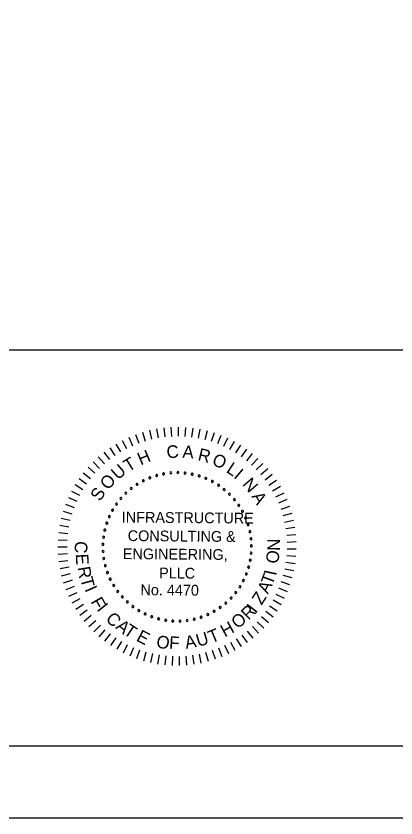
# Model space of a CAD drawing. Extents: x -121.2 to -24.9, y 6.4 to 65.7.
# Drawn here: x -53.92 to -46.89, y 6.35 to 21.19 of the extents above; entities that cross this region are included whole.
import ezdxf

# ---------------------------------------------------------------- set-up
doc = ezdxf.new("R2010")
doc.units = 0
for name, color, linetype in [('BR_BORDER LINES', 7, 'Continuous'), ('BR_TEXT', 7, 'Continuous'), ('Level 31', 7, 'Continuous')]:
    doc.layers.add(name, color=color, linetype=linetype)

msp = doc.modelspace()

# ---------------------------------------------------------------- linework, layer by layer
at = {"layer": 'BR_BORDER LINES'}
for p, q in [((-60.804, 15.017), (-46.496, 15.017)), ((-116.272, 7.683), (-26.496, 7.683))]:
    msp.add_line(p, q, dxfattribs=at)
at = {"layer": 'BR_TEXT'}
for p, q in [((-51.453, 13.526), (-51.413, 13.36)), ((-51.321, 13.553), (-51.292, 13.386)), ((-51.188, 13.572), (-51.169, 13.403)), ((-51.054, 13.583), (-51.045, 13.413)), ((-50.919, 13.586), (-50.921, 13.416)), ((-50.785, 13.58), (-50.796, 13.411)), ((-50.651, 13.567), (-50.673, 13.399)), ((-50.518, 13.545), (-50.55, 13.378)), ((-50.387, 13.515), (-50.429, 13.351)), ((-51.835, 13.396), (-51.766, 13.241)), ((-51.711, 13.447), (-51.651, 13.288)), ((-51.583, 13.49), (-51.533, 13.328)), ((-50.257, 13.478), (-50.31, 13.316)), ((-50.131, 13.432), (-50.193, 13.274)), ((-50.007, 13.379), (-50.079, 13.225)), ((-52.074, 13.272), (-51.987, 13.127)), ((-51.957, 13.338), (-51.878, 13.187)), ((-49.887, 13.318), (-49.968, 13.169)), ((-49.77, 13.251), (-49.86, 13.106)), ((-52.296, 13.12), (-52.192, 12.986)), ((-52.187, 13.2), (-52.091, 13.06)), ((-49.659, 13.176), (-49.757, 13.037)), ((-49.551, 13.094), (-49.658, 12.962)), ((-52.498, 12.942), (-52.378, 12.822)), ((-52.4, 13.034), (-52.287, 12.907)), ((-49.449, 13.006), (-49.564, 12.881)), ((-52.59, 12.844), (-52.463, 12.732)), ((-49.353, 12.913), (-49.475, 12.794)), ((-49.262, 12.813), (-49.391, 12.702)), ((-52.757, 12.633), (-52.617, 12.536)), ((-52.677, 12.741), (-52.543, 12.636)), ((-49.178, 12.708), (-49.313, 12.606)), ((-52.83, 12.52), (-52.684, 12.432)), ((-49.1, 12.598), (-49.242, 12.504)), ((-49.029, 12.484), (-49.176, 12.398)), ((-52.896, 12.402), (-52.745, 12.324)), ((-48.966, 12.365), (-49.117, 12.289)), ((-52.954, 12.281), (-52.799, 12.212)), ((-48.909, 12.243), (-49.065, 12.176)), ((-53.049, 12.029), (-52.887, 11.98)), ((-53.006, 12.157), (-52.847, 12.097)), ((-48.86, 12.117), (-49.02, 12.06)), ((-53.085, 11.9), (-52.92, 11.86)), ((-48.819, 11.989), (-48.982, 11.942)), ((-53.113, 11.768), (-52.946, 11.738)), ((-48.786, 11.859), (-48.951, 11.822)), ((-53.132, 11.635), (-52.964, 11.615)), ((-48.76, 11.727), (-48.928, 11.7)), ((-48.743, 11.593), (-48.912, 11.576)), ((-53.144, 11.501), (-52.974, 11.491)), ((-48.734, 11.459), (-48.904, 11.452)), ((-53.147, 11.366), (-52.978, 11.367)), ((-48.734, 11.324), (-48.903, 11.328)), ((-53.142, 11.231), (-52.973, 11.243)), ((-48.741, 11.19), (-48.91, 11.204)), ((-53.129, 11.097), (-52.961, 11.119)), ((-53.108, 10.965), (-52.941, 10.997)), ((-48.757, 11.056), (-48.925, 11.081)), ((-53.079, 10.833), (-52.914, 10.875)), ((-48.812, 10.793), (-48.976, 10.838)), ((-48.78, 10.923), (-48.947, 10.958)), ((-53.042, 10.704), (-52.88, 10.756)), ((-48.852, 10.664), (-49.013, 10.719)), ((-52.997, 10.577), (-52.838, 10.639)), ((-48.899, 10.538), (-49.056, 10.603)), ((-52.944, 10.453), (-52.79, 10.524)), ((-52.884, 10.333), (-52.734, 10.413)), ((-48.954, 10.415), (-49.107, 10.489)), ((-52.816, 10.216), (-52.672, 10.306)), ((-49.086, 10.181), (-49.229, 10.273)), ((-49.017, 10.296), (-49.165, 10.379)), ((-52.742, 10.104), (-52.603, 10.202)), ((-52.661, 9.996), (-52.529, 10.103)), ((-49.163, 10.07), (-49.3, 10.17)), ((-52.573, 9.894), (-52.448, 10.008)), ((-49.335, 9.863), (-49.459, 9.98)), ((-49.246, 9.964), (-49.376, 10.073)), ((-52.48, 9.797), (-52.362, 9.919)), ((-52.381, 9.706), (-52.27, 9.835)), ((-49.532, 9.679), (-49.64, 9.81)), ((-49.431, 9.768), (-49.547, 9.892)), ((-52.276, 9.622), (-52.173, 9.757)), ((-52.166, 9.543), (-52.072, 9.685)), ((-49.749, 9.521), (-49.841, 9.663)), ((-49.638, 9.597), (-49.738, 9.734)), ((-52.052, 9.472), (-51.967, 9.619)), ((-51.934, 9.408), (-51.858, 9.56)), ((-51.812, 9.351), (-51.745, 9.507)), ((-49.984, 9.389), (-50.058, 9.542)), ((-49.864, 9.451), (-49.947, 9.6)), ((-51.687, 9.302), (-51.629, 9.461)), ((-51.559, 9.26), (-51.511, 9.423)), ((-51.428, 9.226), (-51.391, 9.392)), ((-51.296, 9.2), (-51.269, 9.368)), ((-50.626, 9.194), (-50.65, 9.362)), ((-50.493, 9.217), (-50.528, 9.384)), ((-50.362, 9.249), (-50.407, 9.412)), ((-50.233, 9.288), (-50.288, 9.449)), ((-50.107, 9.335), (-50.171, 9.492)), ((-51.163, 9.183), (-51.146, 9.352)), ((-51.028, 9.173), (-51.022, 9.343)), ((-50.894, 9.172), (-50.898, 9.342)), ((-50.759, 9.179), (-50.773, 9.348))]:
    msp.add_line(p, q, dxfattribs=at)
for centre, start, end in [((-51.445, 12.647), 21.6807, 201.6807), ((-51.445, 12.647), 201.6807, 21.6807), ((-51.319, 12.689), 16.1422, 196.1422), ((-51.319, 12.689), 196.1422, 16.1422), ((-51.19, 12.72), 10.6038, 190.6038), ((-51.19, 12.72), 190.6038, 10.6038), ((-51.058, 12.738), 5.0653, 185.0653), ((-51.058, 12.738), 185.0653, 5.0653), ((-50.926, 12.743), 359.5268, 179.5268), ((-50.926, 12.743), 179.5268, 359.5268), ((-50.793, 12.735), 353.9884, 173.9884), ((-50.793, 12.735), 173.9884, 353.9884), ((-50.662, 12.714), 348.4499, 168.4499), ((-50.662, 12.714), 168.4499, 348.4499), ((-50.533, 12.681), 162.9114, 342.9114), ((-50.533, 12.681), 342.9114, 162.9114), ((-50.408, 12.636), 157.373, 337.373), ((-50.408, 12.636), 337.373, 157.373), ((-51.682, 12.526), 32.7576, 212.7576), ((-51.682, 12.526), 212.7576, 32.7576), ((-51.566, 12.592), 27.2191, 207.2191), ((-51.566, 12.592), 207.2191, 27.2191), ((-50.288, 12.579), 151.8345, 331.8345), ((-50.288, 12.579), 331.8345, 151.8345), ((-50.174, 12.51), 146.2961, 326.2961), ((-50.174, 12.51), 326.2961, 146.2961), ((-51.89, 12.362), 43.8345, 223.8345), ((-51.89, 12.362), 223.8345, 43.8345), ((-51.79, 12.449), 38.2961, 218.2961), ((-51.79, 12.449), 218.2961, 38.2961), ((-50.068, 12.431), 140.7576, 320.7576), ((-50.068, 12.431), 320.7576, 140.7576), ((-49.969, 12.342), 135.2191, 315.2191), ((-49.969, 12.342), 315.2191, 135.2191), ((-52.063, 12.16), 54.9114, 234.9114), ((-52.063, 12.16), 234.9114, 54.9114), ((-51.982, 12.265), 49.373, 229.373), ((-51.982, 12.265), 229.373, 49.373), ((-49.88, 12.244), 129.6807, 309.6807), ((-49.88, 12.244), 309.6807, 129.6807), ((-52.135, 12.048), 60.4499, 240.4499), ((-52.135, 12.048), 240.4499, 60.4499), ((-49.8, 12.137), 124.1422, 304.1422), ((-49.8, 12.137), 304.1422, 124.1422), ((-49.731, 12.024), 118.6038, 298.6038), ((-49.731, 12.024), 298.6038, 118.6038), ((-52.195, 11.93), 65.9884, 245.9884), ((-52.195, 11.93), 245.9884, 65.9884), ((-49.673, 11.904), 113.0653, 293.0653), ((-49.673, 11.904), 293.0653, 113.0653), ((-52.243, 11.806), 71.5268, 251.5268), ((-52.243, 11.806), 251.5268, 71.5268), ((-49.628, 11.779), 107.5268, 287.5268), ((-49.628, 11.779), 287.5268, 107.5268), ((-52.279, 11.678), 77.0653, 257.0653), ((-52.279, 11.678), 257.0653, 77.0653), ((-49.594, 11.651), 101.9884, 281.9884), ((-49.594, 11.651), 281.9884, 101.9884), ((-52.314, 11.415), 88.1422, 268.1422), ((-52.303, 11.547), 82.6038, 262.6038), ((-52.314, 11.415), 268.1422, 88.1422), ((-52.303, 11.547), 262.6038, 82.6038), ((-49.573, 11.519), 96.4499, 276.4499), ((-49.573, 11.519), 276.4499, 96.4499), ((-52.312, 11.282), 93.6807, 273.6807), ((-52.312, 11.282), 273.6807, 93.6807), ((-49.565, 11.387), 90.9114, 270.9114), ((-49.565, 11.387), 270.9114, 90.9114), ((-52.298, 11.15), 99.2191, 279.2191), ((-52.298, 11.15), 279.2191, 99.2191), ((-49.587, 11.122), 79.8345, 259.8345), ((-49.587, 11.122), 259.8345, 79.8345), ((-49.569, 11.254), 85.373, 265.373), ((-49.569, 11.254), 265.373, 85.373), ((-52.27, 11.02), 104.7576, 284.7576), ((-52.27, 11.02), 284.7576, 104.7576), ((-49.617, 10.993), 74.2961, 254.2961), ((-49.617, 10.993), 254.2961, 74.2961), ((-52.231, 10.893), 110.2961, 290.2961), ((-52.231, 10.893), 290.2961, 110.2961), ((-49.659, 10.867), 68.7576, 248.7576), ((-49.659, 10.867), 248.7576, 68.7576), ((-52.179, 10.771), 115.8345, 295.8345), ((-52.179, 10.771), 295.8345, 115.8345), ((-49.713, 10.746), 63.2191, 243.2191), ((-49.713, 10.746), 243.2191, 63.2191), ((-52.115, 10.654), 121.373, 301.373), ((-52.115, 10.654), 301.373, 121.373), ((-52.041, 10.544), 126.9114, 306.9114), ((-52.041, 10.544), 306.9114, 126.9114), ((-49.856, 10.522), 52.1422, 232.1422), ((-49.779, 10.63), 57.6807, 237.6807), ((-49.779, 10.63), 237.6807, 57.6807), ((-51.956, 10.441), 132.4499, 312.4499), ((-51.956, 10.441), 312.4499, 132.4499), ((-49.942, 10.421), 46.6038, 226.6038), ((-49.942, 10.421), 226.6038, 46.6038), ((-49.856, 10.522), 232.1422, 52.1422), ((-51.862, 10.348), 137.9884, 317.9884), ((-51.862, 10.348), 317.9884, 137.9884), ((-51.759, 10.263), 143.5268, 323.5268), ((-51.759, 10.263), 323.5268, 143.5268), ((-50.143, 10.247), 35.5268, 215.5268), ((-50.143, 10.247), 215.5268, 35.5268), ((-50.038, 10.329), 41.0653, 221.0653), ((-50.038, 10.329), 221.0653, 41.0653), ((-51.649, 10.189), 149.0653, 329.0653), ((-51.649, 10.189), 329.0653, 149.0653), ((-51.532, 10.126), 154.6038, 334.6038), ((-51.532, 10.126), 334.6038, 154.6038), ((-50.373, 10.115), 24.4499, 204.4499), ((-50.373, 10.115), 204.4499, 24.4499), ((-50.255, 10.175), 29.9884, 209.9884), ((-50.255, 10.175), 209.9884, 29.9884), ((-51.409, 10.075), 160.1422, 340.1422), ((-51.409, 10.075), 340.1422, 160.1422), ((-51.283, 10.036), 345.6807, 165.6807), ((-51.283, 10.036), 165.6807, 345.6807), ((-51.152, 10.009), 351.2191, 171.2191), ((-51.152, 10.009), 171.2191, 351.2191), ((-51.02, 9.995), 356.7576, 176.7576), ((-51.02, 9.995), 176.7576, 356.7576), ((-50.887, 9.993), 2.2961, 182.2961), ((-50.887, 9.993), 182.2961, 2.2961), ((-50.755, 10.005), 7.8345, 187.8345), ((-50.755, 10.005), 187.8345, 7.8345), ((-50.624, 10.029), 13.373, 193.373), ((-50.624, 10.029), 193.373, 13.373), ((-50.497, 10.066), 18.9114, 198.9114), ((-50.497, 10.066), 198.9114, 18.9114)]:
    msp.add_arc(centre, 0.0187, start, end, dxfattribs=at)
at = {"layer": 'Level 31'}
msp.add_lwpolyline([(-121.161, 6.35), (-25.161, 6.35), (-25.161, 65.017), (-121.161, 65.017)], close=True, dxfattribs=at)

# ---------------------------------------------------------------- texts
at = {"layer": 'BR_TEXT'}
for s, height, rotation, p in [('C', 0.233, 4.7281, (-51.127, 13.006)), ('A', 0.233, 355.6981, (-50.848, 13.019)), ('H', 0.233, 22.7882, (-51.615, 12.874)), ('R', 0.233, 346.6681, (-50.57, 12.974)), ('O', 0.233, 337.638, (-50.31, 12.894)), ('T', 0.233, 31.8182, (-51.841, 12.747)), ('L', 0.233, 327.108, (-50.046, 12.759)), ('U', 0.233, 40.8482, (-52.036, 12.597)), ('I', 0.233, 319.578, (-49.906, 12.659)), ('O', 0.233, 49.8782, (-52.215, 12.408)), ('N', 0.233, 310.548, (-49.744, 12.523)), ('S', 0.233, 58.9083, (-52.363, 12.199)), ('A', 0.233, 301.5179, (-49.57, 12.303)), ('INFRASTRUCTURE', 0.19939, 359.5268, (-51.966, 11.819)), ('CONSULTING &', 0.19939, 359.5268, (-51.856, 11.476)), ('C', 0.233, 267.025, (-52.829, 11.479)), ('N', 0.233, 89.2085, (-49.039, 11.293)), ('ENGINEERING,', 0.19939, 359.5268, (-51.946, 11.142)), ('O', 0.233, 83.2085, (-49.068, 11.05)), ('E', 0.233, 273.025, (-52.818, 11.235)), ('R', 0.233, 279.025, (-52.784, 10.989)), ('PLLC', 0.1994, 359.5268, (-51.275, 10.786)), ('T', 0.233, 69.3954, (-49.178, 10.645)), ('I', 0.233, 77.9093, (-49.11, 10.825)), ('T', 0.233, 285.025, (-52.737, 10.779)), ('A', 0.233, 63.3954, (-49.26, 10.484)), ('I', 0.233, 293.7713, (-52.658, 10.584)), ('No. 4470', 0.1994, 359.5268, (-51.62, 10.474)), ('Z', 0.233, 57.3954, (-49.377, 10.28)), ('F', 0.233, 299.7713, (-52.548, 10.355)), ('I', 0.233, 308.5268, (-52.436, 10.211)), ('R', 0.233, 44.5268, (-49.619, 10)), ('I', 0.233, 52.3339, (-49.487, 10.127)), ('C', 0.233, 314.5268, (-52.278, 10.024)), ('O', 0.233, 38.5268, (-49.823, 9.841)), ('A', 0.233, 320.5268, (-52.093, 9.868)), ('T', 0.233, 326.5268, (-51.948, 9.765)), ('H', 0.233, 28.5268, (-50.058, 9.691)), ('E', 0.233, 332.5268, (-51.712, 9.638)), ('T', 0.233, 22.5268, (-50.306, 9.58)), ('O', 0.233, 350.5268, (-51.338, 9.508)), ('F', 0.233, 356.5268, (-51.094, 9.483)), ('A', 0.233, 10.5268, (-50.775, 9.479)), ('U', 0.233, 16.5268, (-50.551, 9.515))]:
    msp.add_text(s, height=height, rotation=rotation, dxfattribs=at).set_placement(p)

doc.saveas('drawing.dxf')
